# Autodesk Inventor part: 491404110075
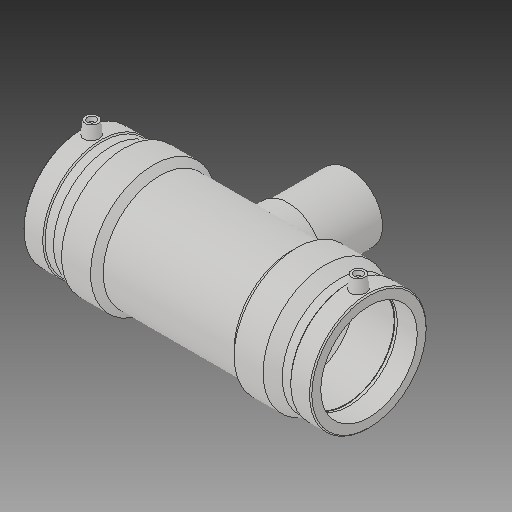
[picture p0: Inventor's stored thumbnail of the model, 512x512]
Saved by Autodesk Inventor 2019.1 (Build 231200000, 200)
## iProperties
Created: 2017-06
Part Number: 491404110075
Material: Generic
Description: PLASSON REDUCING TEE 110x75x111
Document SubType Name: Modeling
Designer: KIM
Mass: 5000.41 g
Surface Area: 5471.45 cm^2
Volume: 5000.41 cm^3
Density: 1 g/cm^3
Appearance: Default
Author: KIM
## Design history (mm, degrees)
derived "491404.ipt"
feature "Solid1::491404.ipt"
tag "TaggingFeature1"
body "Solid1"
other parameters: "d0" = 328, "d2" = 143, "d3" = 72, "d4" = 65.6, "d5" = 128.7, "d6" = 104.5, "d8" = 168 deg, "d10" = 28.8, "d11" = 9.6, "d13" = 328, "d14" = 17.6296, "d17" = 99, "d19" = 3.52592, "d20" = 168 deg, "d22" = 132.99, "d23" = 143, "d25" = 135 deg, "d26" = 229.6, "d29" = 81, "d30" = 15, "d31" = 131.2, "d34" = 5 deg, "d35" = 15, "d39" = 5 deg, "d41" = 4, "d42" = 14, "d43" = 0, "d45" = 4, "d46" = 6, "d47" = 0, "d48" = -142, "d49" = 75, "d51" = 0, "d54" = 0, "d55" = 128.7, "d56" = 143, "d57" = 114.8, "d58" = 135 deg, "d59" = 72, "d60" = 72, "d61" = 135 deg, "d62" = 142, "d72" = 149.24, "d73" = 74.62, "d74" = -142, "d75" = 78.75, "d77" = 0, "d80" = 0, "d81" = 75, "d82" = 70.5, "d83" = 0, "d84" = 3, "d85" = 0, "d86" = 24, "d87" = 130.3302, "d88" = 9.6, "d89" = 3, "d90" = 0, "L_" = 328, "L_1" = 72, "D_" = 143, "A_" = 81, "d_2" = 12, "H_" = 142, "d_1" = 75
